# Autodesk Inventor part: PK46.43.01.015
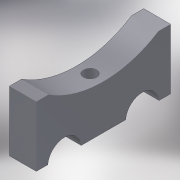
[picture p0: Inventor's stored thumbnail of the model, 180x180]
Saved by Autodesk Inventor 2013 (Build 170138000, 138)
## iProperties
Shininess: 64.0
Length Units: 11269
Angle Units: 11279
Time Units: 11290
Mass Units: 11283
Length Display Precision: 3
Angle Display Precision: 2
Compacted: True
Part Number: PK46.43.01.015
Document SubType Name: Modeling
Created: 2004-12
Material: Сталь высокопрочная низколегированная
Designer: ELarisa
Manufacturer: Standard
Standards Organization: Custom
Density: 7.84 g/cm^3
Density: 0.0
Volumn: 0.0
Area: 0.0
PropertySet Name: Model Information
Control State: 0
Master: False
Checked Out: False
Checked Out Date: 2008-10-09
Last Check In Date: 2008-10-09
Author: ELarisa
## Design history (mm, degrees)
sketch "Эскиз3"
  geometry: L1 (-52.305, -27.794)-(-52.305, -72.794); L2 (47.695, -72.794)-(47.695, -27.794); L3 (47.695, -27.794)-(38.682, -27.794); L4 (-43.293, -27.794)-(-52.305, -27.794); L5 (-52.305, -72.794)-(-43.765, -72.794); L6 (-18.846, -72.794)-(14.235, -72.794); L7 (39.154, -72.794)-(47.695, -72.794); A1 r 76 centre (-2.305, 36.206) between (-43.293, -27.794) and (38.682, -27.794); A2 r 12.5 centre (-31.305, -73.794) between (-18.846, -72.794) and (-43.765, -72.794); A3 r 12.5 centre (26.695, -73.794) between (39.154, -72.794) and (14.235, -72.794)
  constraints: 14 end point, 7 parallel, 6 point on circle, 3 centre point, 3 perpendicular, 2 collinear, 1 vertical
  dimensions: "d24" = 45 distance of L1.start L1.end; "d25" = 76 radius of A1; "d26" = 109 distance from line of L6 A1.centre; "d27" = 45 distance of L2.start L2.end; "d28" = 1 distance from line of A2.centre L5; "d29" = 1 distance from line of L7 A3.centre; "d30" = 50 distance from line of A1.centre L1; "d31" = 58 distance of A3.centre A2.centre; "d32" = 12.5 radius of A2; "d33" = 12.5 radius of A3; "d34" = 100 distance between parallel lines of L2 L1; "d35" = 21 distance from line of A2.centre L1
extrude "Выдавливание3" new body sketch "Эскиз3" distance "d36" = 20; taper "d37" = 0 deg
sketch "Эскиз4"
  geometry: L1 (-20, 33.08)-(-20, 0) reference; L2 (0, -33.46)-(-20, -33.46) reference; 1 further point
  dimensions: "d39" = 50 distance from line of point (-10, 16.54) L2; "d40" = 10 distance from line of point (-10, 16.54) L1
hole "Отверстие1" sketch "Эскиз4" diameter "d41" = 10.106; stored, may be unused: countersink angle "d45" = 90 deg, drill point angle "d47" = 118 deg; dims "d42" = 26, "d43" = 15.2, "d44" = 2, "d46" = 26
body "Solid1"
other parameters: "d9" = 34, "d10" = 34
